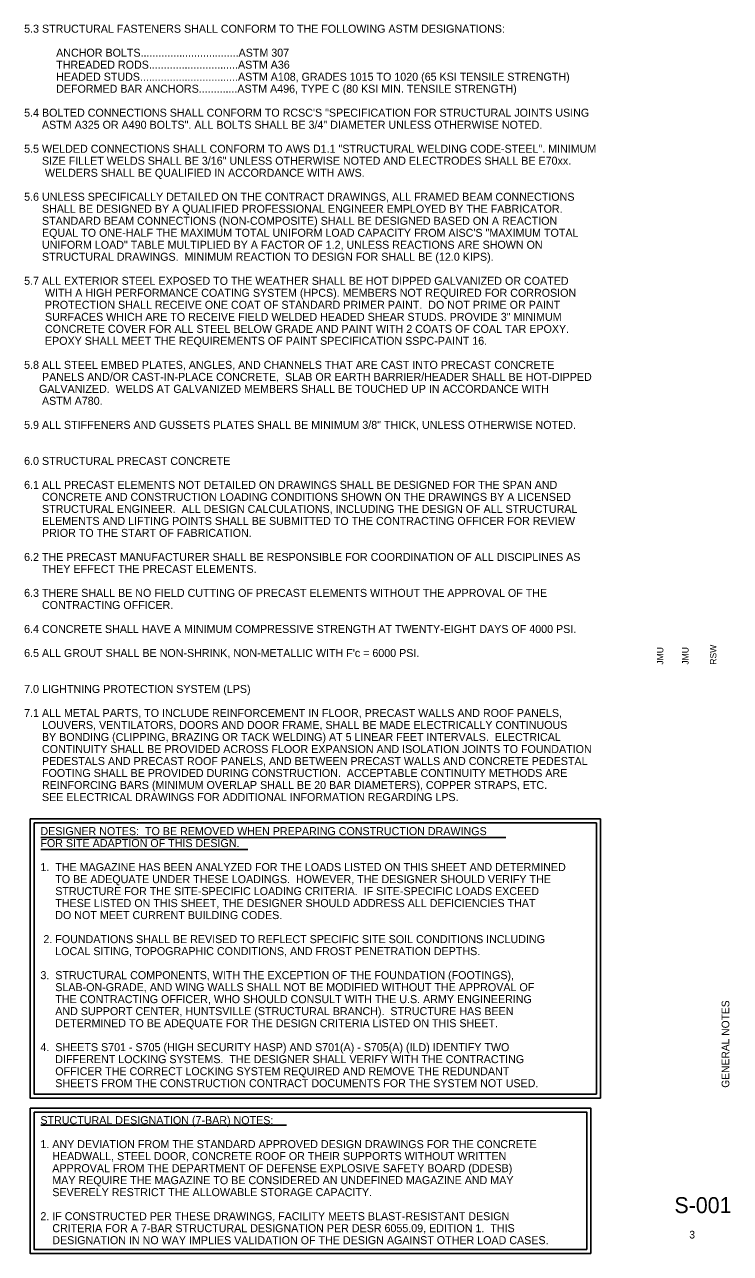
# Model space of a CAD drawing. Extents: x 0.17 to 2.69, y 0.12 to 1.72.
# Drawn here: x 1.771 to 2.69, y 0.119 to 1.718 of the extents above; entities that cross this region are included whole.
import ezdxf

# ---------------------------------------------------------------- set-up
doc = ezdxf.new("R2010")
doc.units = 0
doc.layers.add('G-ANNO-TEXT', color=7, linetype='Continuous')
doc.layers.add('G-ANNO-TTLB', color=7, linetype='Continuous')

msp = doc.modelspace()

# ---------------------------------------------------------------- linework, layer by layer
at = {"layer": 'G-ANNO-TEXT'}
for p, q in [((1.7925, 0.66), (2.3978, 0.66)), ((1.7925, 0.6443), (2.062, 0.6443)), ((1.7925, 0.2856), (2.1125, 0.2856))]:
    msp.add_line(p, q, dxfattribs=at)
for points in [[(1.7783, 0.6842), (2.5212, 0.6842), (2.5212, 0.321), (1.7783, 0.321)], [(1.7835, 0.679), (2.516, 0.679), (2.516, 0.3262), (1.7835, 0.3262)], [(1.7783, 0.308), (2.5086, 0.308), (2.5086, 0.1188), (1.7783, 0.1188)], [(1.7835, 0.3027), (2.5034, 0.3027), (2.5034, 0.124), (1.7835, 0.124)]]:
    msp.add_lwpolyline(points, close=True, dxfattribs=at)

# ---------------------------------------------------------------- texts
for s, height, p in [('5.3 STRUCTURAL FASTENERS SHALL CONFORM TO THE FOLLOWING ASTM DESIGNATIONS:', 0.010417, (1.7706, 1.7075)), ('ANCHOR BOLTS.................................ASTM 307', 0.010417, (1.8123, 1.6763)), ('THREADED RODS..............................ASTM A36', 0.010417, (1.8123, 1.6607)), ('HEADED STUDS.................................ASTM A108, GRADES 1015 TO 1020 (65 KSI TENSILE STRENGTH)', 0.0104167, (1.8123, 1.645)), ('DEFORMED BAR ANCHORS.............ASTM A496, TYPE C (80 KSI MIN. TENSILE STRENGTH)', 0.010417, (1.8123, 1.6294)), ('5.4 BOLTED CONNECTIONS SHALL CONFORM TO RCSC\'S "SPECIFICATION FOR STRUCTURAL JOINTS USING', 0.010417, (1.7706, 1.5982)), ('      ASTM A325 OR A490 BOLTS". ALL BOLTS SHALL BE 3/4" DIAMETER UNLESS OTHERWISE NOTED.', 0.010417, (1.7706, 1.5825)), ('5.5 WELDED CONNECTIONS SHALL CONFORM TO AWS D1.1 "STRUCTURAL WELDING CODE-STEEL". MINIMUM', 0.010417, (1.7706, 1.5513)), ('      SIZE FILLET WELDS SHALL BE 3/16" UNLESS OTHERWISE NOTED AND ELECTRODES SHALL BE E70xx. ', 0.010417, (1.7706, 1.5357)), ('       WELDERS SHALL BE QUALIFIED IN ACCORDANCE WITH AWS.', 0.010417, (1.7706, 1.52)), ('5.6 UNLESS SPECIFICALLY DETAILED ON THE CONTRACT DRAWINGS, ALL FRAMED BEAM CONNECTIONS ', 0.010417, (1.7706, 1.4888)), ('      SHALL BE DESIGNED BY A QUALIFIED PROFESSIONAL ENGINEER EMPLOYED BY THE FABRICATOR.', 0.010417, (1.7706, 1.4732)), ('      STANDARD BEAM CONNECTIONS (NON-COMPOSITE) SHALL BE DESIGNED BASED ON A REACTION ', 0.010417, (1.7706, 1.4575)), ('      EQUAL TO ONE-HALF THE MAXIMUM TOTAL UNIFORM LOAD CAPACITY FROM AISC\'S "MAXIMUM TOTAL', 0.010417, (1.7706, 1.4419)), ('      UNIFORM LOAD" TABLE MULTIPLIED BY A FACTOR OF 1.2, UNLESS REACTIONS ARE SHOWN ON ', 0.010417, (1.7706, 1.4263)), ('      STRUCTURAL DRAWINGS.  MINIMUM REACTION TO DESIGN FOR SHALL BE (12.0 KIPS). ', 0.010417, (1.7706, 1.4107)), ('5.7 ALL EXTERIOR STEEL EXPOSED TO THE WEATHER SHALL BE HOT DIPPED GALVANIZED OR COATED', 0.010417, (1.7706, 1.3794)), ('       WITH A HIGH PERFORMANCE COATING SYSTEM (HPCS). MEMBERS NOT REQUIRED FOR CORROSION', 0.010417, (1.7706, 1.3638)), ('       PROTECTION SHALL RECEIVE ONE COAT OF STANDARD PRIMER PAINT.  DO NOT PRIME OR PAINT', 0.010417, (1.7706, 1.3482)), ('       SURFACES WHICH ARE TO RECEIVE FIELD WELDED HEADED SHEAR STUDS. PROVIDE 3" MINIMUM', 0.010417, (1.7706, 1.3325)), ('       CONCRETE COVER FOR ALL STEEL BELOW GRADE AND PAINT WITH 2 COATS OF COAL TAR EPOXY.', 0.010417, (1.7706, 1.3169)), ('       EPOXY SHALL MEET THE REQUIREMENTS OF PAINT SPECIFICATION SSPC-PAINT 16.   ', 0.010417, (1.7706, 1.3013)), ('5.8 ALL STEEL EMBED PLATES, ANGLES, AND CHANNELS THAT ARE CAST INTO PRECAST CONCRETE ', 0.010417, (1.7706, 1.27)), ('      PANELS AND/OR CAST-IN-PLACE CONCRETE,  SLAB OR EARTH BARRIER/HEADER SHALL BE HOT-DIPPED', 0.010417, (1.7706, 1.2544)), ('     GALVANIZED.  WELDS AT GALVANIZED MEMBERS SHALL BE TOUCHED UP IN ACCORDANCE WITH ', 0.010417, (1.7706, 1.2388)), ('      ASTM A780.', 0.010417, (1.7706, 1.2232)), ('5.9 ALL STIFFENERS AND GUSSETS PLATES SHALL BE MINIMUM 3/8" THICK, UNLESS OTHERWISE NOTED. ', 0.010417, (1.7706, 1.1919)), ('6.0 STRUCTURAL PRECAST CONCRETE', 0.010417, (1.7706, 1.145)), ('6.1 ALL PRECAST ELEMENTS NOT DETAILED ON DRAWINGS SHALL BE DESIGNED FOR THE SPAN AND', 0.010417, (1.7706, 1.1138)), ('      CONCRETE AND CONSTRUCTION LOADING CONDITIONS SHOWN ON THE DRAWINGS BY A LICENSED', 0.010417, (1.7706, 1.0982)), ('      STRUCTURAL ENGINEER.  ALL DESIGN CALCULATIONS, INCLUDING THE DESIGN OF ALL STRUCTURAL', 0.010417, (1.7706, 1.0825)), ('      ELEMENTS AND LIFTING POINTS SHALL BE SUBMITTED TO THE CONTRACTING OFFICER FOR REVIEW', 0.010417, (1.7706, 1.0669)), ('      PRIOR TO THE START OF FABRICATION.', 0.010417, (1.7706, 1.0513)), ('6.2 THE PRECAST MANUFACTURER SHALL BE RESPONSIBLE FOR COORDINATION OF ALL DISCIPLINES AS', 0.010417, (1.7706, 1.02)), ('      THEY EFFECT THE PRECAST ELEMENTS.', 0.010417, (1.7706, 1.0044)), ('6.3 THERE SHALL BE NO FIELD CUTTING OF PRECAST ELEMENTS WITHOUT THE APPROVAL OF THE', 0.010417, (1.7706, 0.9732)), ('      CONTRACTING OFFICER.', 0.010417, (1.7706, 0.9575)), ('6.4 CONCRETE SHALL HAVE A MINIMUM COMPRESSIVE STRENGTH AT TWENTY-EIGHT DAYS OF 4000 PSI.', 0.010417, (1.7706, 0.9263)), ("6.5 ALL GROUT SHALL BE NON-SHRINK, NON-METALLIC WITH F'c = 6000 PSI.", 0.010417, (1.7706, 0.895)), ('7.0 LIGHTNING PROTECTION SYSTEM (LPS)', 0.010417, (1.7706, 0.8482)), ('7.1 ALL METAL PARTS, TO INCLUDE REINFORCEMENT IN FLOOR, PRECAST WALLS AND ROOF PANELS,', 0.010417, (1.7706, 0.8169)), ('      LOUVERS, VENTILATORS, DOORS AND DOOR FRAME, SHALL BE MADE ELECTRICALLY CONTINUOUS', 0.010417, (1.7706, 0.8013)), ('      BY BONDING (CLIPPING, BRAZING OR TACK WELDING) AT 5 LINEAR FEET INTERVALS.  ELECTRICAL ', 0.010417, (1.7706, 0.7857)), ('      CONTINUITY SHALL BE PROVIDED ACROSS FLOOR EXPANSION AND ISOLATION JOINTS TO FOUNDATION', 0.010417, (1.7706, 0.77)), ('      PEDESTALS AND PRECAST ROOF PANELS, AND BETWEEN PRECAST WALLS AND CONCRETE PEDESTAL', 0.010417, (1.7706, 0.7544)), ('      FOOTING SHALL BE PROVIDED DURING CONSTRUCTION.  ACCEPTABLE CONTINUITY METHODS ARE', 0.010417, (1.7706, 0.7388)), ('      REINFORCING BARS (MINIMUM OVERLAP SHALL BE 20 BAR DIAMETERS), COPPER STRAPS, ETC.', 0.010417, (1.7706, 0.7232)), ('      SEE ELECTRICAL DRAWINGS FOR ADDITIONAL INFORMATION REGARDING LPS.', 0.010417, (1.7706, 0.7075)), ('DESIGNER NOTES:  TO BE REMOVED WHEN PREPARING CONSTRUCTION DRAWINGS ', 0.010417, (1.7918, 0.6632)), ('FOR SITE ADAPTION OF THIS DESIGN.', 0.010417, (1.7918, 0.6476)), ('1.  THE MAGAZINE HAS BEEN ANALYZED FOR THE LOADS LISTED ON THIS SHEET AND DETERMINED', 0.010417, (1.7918, 0.6164)), ('     TO BE ADEQUATE UNDER THESE LOADINGS.  HOWEVER, THE DESIGNER SHOULD VERIFY THE ', 0.010417, (1.7918, 0.6007)), ('     STRUCTURE FOR THE SITE-SPECIFIC LOADING CRITERIA.  IF SITE-SPECIFIC LOADS EXCEED ', 0.010417, (1.7918, 0.5851)), ('     THESE LISTED ON THIS SHEET, THE DESIGNER SHOULD ADDRESS ALL DEFICIENCIES THAT', 0.010417, (1.7918, 0.5695)), ('     DO NOT MEET CURRENT BUILDING CODES. ', 0.010417, (1.7918, 0.5539)), (' 2. FOUNDATIONS SHALL BE REVISED TO REFLECT SPECIFIC SITE SOIL CONDITIONS INCLUDING', 0.010417, (1.7918, 0.5226)), ('     LOCAL SITING, TOPOGRAPHIC CONDITIONS, AND FROST PENETRATION DEPTHS.', 0.010417, (1.7918, 0.507)), ('3.  STRUCTURAL COMPONENTS, WITH THE EXCEPTION OF THE FOUNDATION (FOOTINGS),', 0.010417, (1.7918, 0.4757)), ('     SLAB-ON-GRADE, AND WING WALLS SHALL NOT BE MODIFIED WITHOUT THE APPROVAL OF', 0.010417, (1.7918, 0.4601)), ('     THE CONTRACTING OFFICER, WHO SHOULD CONSULT WITH THE U.S. ARMY ENGINEERING', 0.010417, (1.7918, 0.4445)), ('     AND SUPPORT CENTER, HUNTSVILLE (STRUCTURAL BRANCH).  STRUCTURE HAS BEEN', 0.010417, (1.7918, 0.4289)), ('     DETERMINED TO BE ADEQUATE FOR THE DESIGN CRITERIA LISTED ON THIS SHEET.    ', 0.010417, (1.7918, 0.4132)), ('4.  SHEETS S701 - S705 (HIGH SECURITY HASP) AND S701(A) - S705(A) (ILD) IDENTIFY TWO', 0.010417, (1.7918, 0.382)), ('     DIFFERENT LOCKING SYSTEMS.  THE DESIGNER SHALL VERIFY WITH THE CONTRACTING', 0.010417, (1.7918, 0.3664)), ('     OFFICER THE CORRECT LOCKING SYSTEM REQUIRED AND REMOVE THE REDUNDANT', 0.010417, (1.7918, 0.3507)), ('     SHEETS FROM THE CONSTRUCTION CONTRACT DOCUMENTS FOR THE SYSTEM NOT USED.', 0.010417, (1.7918, 0.3351)), ('STRUCTURAL DESIGNATION (7-BAR) NOTES:', 0.010417, (1.7918, 0.287)), ('1. ANY DEVIATION FROM THE STANDARD APPROVED DESIGN DRAWINGS FOR THE CONCRETE', 0.010417, (1.7918, 0.2558)), ('    HEADWALL, STEEL DOOR, CONCRETE ROOF OR THEIR SUPPORTS WITHOUT WRITTEN ', 0.010417, (1.7918, 0.2402)), ('    APPROVAL FROM THE DEPARTMENT OF DEFENSE EXPLOSIVE SAFETY BOARD (DDESB)', 0.010417, (1.7918, 0.2245)), ('    MAY REQUIRE THE MAGAZINE TO BE CONSIDERED AN UNDEFINED MAGAZINE AND MAY ', 0.010417, (1.7918, 0.2089)), ('    SEVERELY RESTRICT THE ALLOWABLE STORAGE CAPACITY.', 0.010417, (1.7918, 0.1933)), ('2. IF CONSTRUCTED PER THESE DRAWINGS, FACILITY MEETS BLAST-RESISTANT DESIGN', 0.010417, (1.7918, 0.162)), ('    CRITERIA FOR A 7-BAR STRUCTURAL DESIGNATION PER DESR 6055.09, EDITION 1.  THIS', 0.010417, (1.7918, 0.1464)), ('    DESIGNATION IN NO WAY IMPLIES VALIDATION OF THE DESIGN AGAINST OTHER LOAD CASES.', 0.010417, (1.7918, 0.1308))]:
    msp.add_text(s, height=height, dxfattribs=at).set_placement(p)
at = {"layer": 'G-ANNO-TTLB'}
for s, height, p in [('JMU', 0.00833, (2.603, 0.885)), ('JMU', 0.00833, (2.6359, 0.885)), ('RSW', 0.00833, (2.6722, 0.885)), ('GENERAL NOTES', 0.01, (2.689, 0.3344))]:
    msp.add_text(s, height=height, rotation=90, dxfattribs=at).set_placement(p)
for s, height, p in [('S-001', 0.02083, (2.6175, 0.1712)), ('3', 0.01, (2.6369, 0.1382))]:
    msp.add_text(s, height=height, dxfattribs=at).set_placement(p)

doc.saveas('drawing.dxf')
